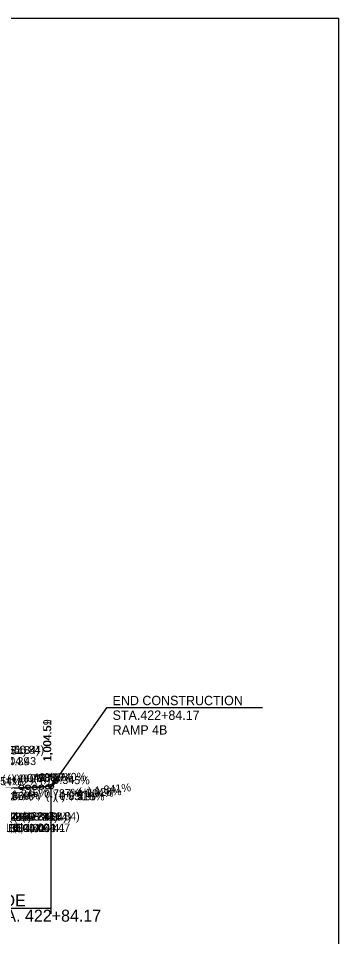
# Model space of a CAD drawing. Extents: x 150 to 16976893, y 3102 to 12559827.
# Drawn here: x 16976652 to 16976893, y 12558849 to 12559538 of the extents above; entities that cross this region are included whole.
import ezdxf

# ---------------------------------------------------------------- set-up
doc = ezdxf.new("R2010")
doc.units = 0
for name, color, linetype in [('Default', 7, 'Continuous'), ('RD_DDB_GradeTX', 7, 'Continuous'), ('RD_DDB_PI', 7, 'Continuous'), ('RD_DDB_Profile_EX', 7, 'Continuous'), ('RD_DDB_StripGrade', 7, 'Continuous'), ('RD_TX_Profile', 7, 'Continuous'), ('RD_XS_Misc_Line', 7, 'Continuous')]:
    doc.layers.add(name, color=color, linetype=linetype)

msp = doc.modelspace()

# ---------------------------------------------------------------- linework, layer by layer
at = {"layer": 'Default'}
msp.add_lwpolyline([(16975392.9, 12558539.31), (16976892.9, 12558539.31), (16976892.9, 12559537.53), (16975392.9, 12559537.53)], close=True, dxfattribs=at)
at = {"layer": 'RD_DDB_PI'}
for centre in [(16976654.74, 12558961.37), (16976659.74, 12558961.29), (16976664.74, 12558961.21), (16976669.74, 12558961.39), (16976674.74, 12558961.64), (16976677.07, 12558961.86)]:
    msp.add_circle(centre, 1.75, dxfattribs=at)
at = {"layer": 'RD_DDB_Profile_EX'}
msp.add_lwpolyline([(16976649.37, 12558960.68), (16976654.37, 12558960.78), (16976659.37, 12558960.98), (16976664.37, 12558961.2), (16976669.37, 12558961.38), (16976674.37, 12558962.18), (16976677.07, 12558962.36)], dxfattribs=at)
at = {"layer": 'RD_DDB_StripGrade'}
for p, q in [((16976677.07, 12558866.45), (16976677.07, 12558961.87)), ((16976567.9, 12558870.61), (16976677.07, 12558870.61))]:
    msp.add_line(p, q, dxfattribs=at)
at = {"layer": 'RD_TX_Profile'}
msp.add_line((16976835.77, 12559020.84), (16976719.19, 12559020.84), dxfattribs=at)
msp.add_lwpolyline([(16976719.19, 12559020.84), (16976718.65, 12559020.84), (16976677.07, 12558961.84)], dxfattribs=at)
msp.add_lwpolyline([(16976679.48, 12558968.41), (16976677.07, 12558961.84), (16976682.44, 12558966.32)], close=True, dxfattribs=at)
at = {"layer": 'RD_XS_Misc_Line'}
msp.add_lwpolyline([(16976567.9, 12558957.61), (16976592.9, 12558958.74), (16976617.9, 12558959.53), (16976642.9, 12558960.53), (16976667.9, 12558961.81), (16976677.07, 12558962.28)], dxfattribs=at)

# ---------------------------------------------------------------- texts
at = {"layer": 'RD_DDB_GradeTX'}
for s, rotation, p in [('(+) 1.040%', 2.97681, (16976640.33, 12558964.3)), ('(+) 0.798%', 2.28546, (16976644.02, 12558964.26)), ('(+) 0.788%', 2.25657, (16976648.9, 12558964.44)), ('(+) 0.778%', 2.22763, (16976654.2, 12558964.64)), ('(+) 0.740%', 2.12001, (16976664.03, 12558964.99)), ('(+) 0.154%', 0.44134, (16976615.37, 12558962.71)), ('(-) 0.345%', 359.0114, (16976668.49, 12558964.13)), ('(+) 0.362%', 1.03832, (16976618.48, 12558950.93)), ('(+) 0.406%', 1.16375, (16976624.15, 12558951.08)), ('(+) 0.509%', 1.45844, (16976628.96, 12558951.27)), ('(+) 1.245%', 3.56286, (16976635.67, 12558952.2)), ('(+) 0.787%', 2.25251, (16976659.67, 12558952.85)), ('(-) 0.330%', 359.05585, (16976673, 12558952.07)), ('(-) 0.313%', 359.10443, (16976679.66, 12558951.98)), ('(+) 0.704%', 2.01638, (16976684.46, 12558952.9)), ('(+) 1.028%', 2.94253, (16976690.59, 12558953.45)), ('(+) 1.841%', 5.25958, (16976697.89, 12558954.74))]:
    msp.add_text(s, height=6, rotation=rotation, dxfattribs=at).set_placement(p)
at = {"layer": 'RD_DDB_PI'}
for s, p in [('1,004.59', (16976677.07, 12558981.03)), ('1,004.51', (16976677.07, 12558980.61))]:
    msp.add_text(s, height=6, rotation=90, dxfattribs=at).set_placement(p)
for s, p in [('VPI  (422+41.84)', (16976597.68, 12558985.88)), ('VPI  (422+51.84)', (16976607.45, 12558986.27)), ('VPI  (422+56.84)', (16976610.91, 12558986.46)), ('El  1,004.39', (16976617.87, 12558977.77)), ('El  1,004.43', (16976622.9, 12558977.96)), ('VPI  (422+46.84)', (16976601.15, 12558936.08)), ('VPI  (422+61.84)', (16976617.68, 12558936.37)), ('VPI  (422+66.84)', (16976621.15, 12558936.29)), ('VPI  (422+71.84)', (16976627.86, 12558936.21)), ('VPI  (422+76.84)', (16976631.33, 12558936.39)), ('VPI  (422+81.84)', (16976637.57, 12558936.64)), ('El  1,004.35', (16976612.66, 12558927.58)), ('El  1,004.41', (16976629.82, 12558927.87)), ('El  1,004.40', (16976633.17, 12558927.79)), ('El  1,004.38', (16976637.78, 12558927.71)), ('El  1,004.41', (16976644.82, 12558927.89)), ('El  1,004.47', (16976648.46, 12558928.14))]:
    msp.add_text(s, height=6, dxfattribs=at).set_placement(p)
at = {"layer": 'RD_DDB_StripGrade'}
for s, p in [('SPLINE GRADE', (16976569.02, 12558872.01)), ('STA. 421+75.00 TO STA. 422+84.17', (16976516.58, 12558860.6))]:
    msp.add_text(s, height=9, dxfattribs=at).set_placement(p)
at = {"layer": 'RD_TX_Profile'}
for s, p in [('END CONSTRUCTION', (16976723.19, 12559022.84)), ('STA.422+84.17 ', (16976723.19, 12559011.84)), ('RAMP 4B', (16976723.19, 12559000.84))]:
    msp.add_text(s, height=7, dxfattribs=at).set_placement(p)

doc.saveas('drawing.dxf')
